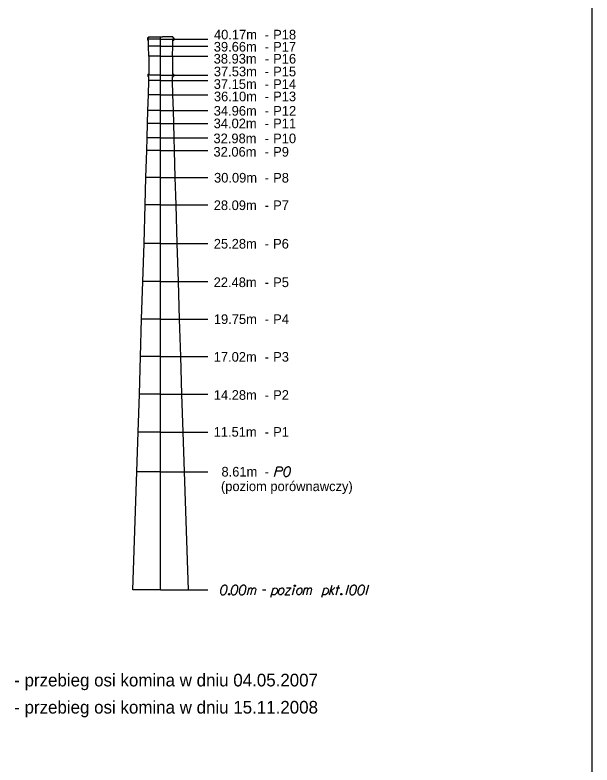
# Model space of a CAD drawing. Extents: x 138 to 264, y -75 to 121.
# Drawn here: x 180.87 to 190.1, y -57.33 to -45.34 of the extents above; entities that cross this region are included whole.
import ezdxf

# ---------------------------------------------------------------- set-up
doc = ezdxf.new("R2010")
doc.units = 0
doc.layers.add('Opisy', color=7, linetype='Continuous')
doc.layers.add('Ramka do drukowania', color=7, linetype='Continuous')

msp = doc.modelspace()

# ---------------------------------------------------------------- linework, layer by layer
at = {"layer": 'Opisy'}
for p, q in [((182.991, -45.703), (182.991, -45.721)), ((183.008, -45.703), (182.991, -45.703)), ((183.008, -45.684), (183.008, -45.703)), ((183.008, -45.684), (183.234, -45.684)), ((183.204, -54.531), (183.204, -45.684)), ((183.4, -45.684), (183.234, -45.684)), ((183.4, -45.684), (183.4, -45.703)), ((183.4, -45.703), (183.417, -45.703)), ((183.417, -45.703), (183.417, -45.721)), ((183.204, -45.721), (182.991, -45.721)), ((182.991, -45.721), (182.991, -45.74)), ((183.008, -45.74), (182.991, -45.74)), ((183.008, -45.834), (183.008, -45.74)), ((183.204, -45.721), (183.957, -45.721)), ((183.4, -45.74), (183.417, -45.74)), ((183.4, -45.834), (183.4, -45.74)), ((183.417, -45.721), (183.417, -45.74)), ((183.204, -45.834), (183.008, -45.834)), ((183.014, -45.994), (183.008, -45.834)), ((183.204, -45.834), (183.957, -45.834)), ((183.394, -45.994), (183.4, -45.834)), ((183.204, -45.994), (183.014, -45.994)), ((183.014, -45.994), (183.014, -46.282)), ((183.204, -45.994), (183.957, -45.994)), ((183.394, -45.994), (183.394, -46.282)), ((183.001, -46.282), (183.001, -46.301)), ((183.001, -46.282), (183.014, -46.282)), ((183.204, -46.301), (183.001, -46.301)), ((183.001, -46.301), (183.001, -46.321)), ((183.204, -46.301), (183.957, -46.301)), ((183.407, -46.282), (183.394, -46.282)), ((183.407, -46.282), (183.407, -46.301)), ((183.407, -46.301), (183.407, -46.321)), ((183.016, -46.321), (183.001, -46.321)), ((183.008, -46.615), (183.014, -46.384)), ((183.014, -46.384), (183.016, -46.321)), ((183.204, -46.384), (183.014, -46.384)), ((183.204, -46.384), (183.957, -46.384)), ((183.394, -46.384), (183.392, -46.321)), ((183.392, -46.321), (183.407, -46.321)), ((183.4, -46.615), (183.394, -46.384)), ((183.001, -46.866), (183.008, -46.615)), ((183.204, -46.615), (183.008, -46.615)), ((183.204, -46.615), (183.957, -46.615)), ((183.407, -46.866), (183.4, -46.615)), ((182.994, -47.071), (183.001, -46.866)), ((183.204, -46.866), (183.001, -46.866)), ((183.204, -46.866), (183.957, -46.866)), ((183.413, -47.071), (183.407, -46.866)), ((182.989, -47.299), (182.994, -47.071)), ((183.204, -47.071), (182.994, -47.071)), ((183.204, -47.071), (183.957, -47.071)), ((183.419, -47.299), (183.413, -47.071)), ((182.981, -47.501), (182.989, -47.299)), ((183.204, -47.299), (182.989, -47.299)), ((183.204, -47.299), (183.957, -47.299)), ((183.426, -47.501), (183.419, -47.299)), ((182.969, -47.933), (182.981, -47.501)), ((183.204, -47.501), (182.981, -47.501)), ((183.204, -47.501), (183.957, -47.501)), ((183.438, -47.933), (183.426, -47.501)), ((182.956, -48.371), (182.969, -47.933)), ((183.204, -47.933), (182.969, -47.933)), ((183.204, -47.933), (183.957, -47.933)), ((183.452, -48.371), (183.438, -47.933)), ((182.939, -48.989), (182.956, -48.371)), ((183.204, -48.371), (182.956, -48.371)), ((183.204, -48.371), (183.957, -48.371)), ((183.469, -48.989), (183.452, -48.371)), ((182.919, -49.601), (182.939, -48.989)), ((183.204, -48.989), (182.939, -48.989)), ((183.204, -48.989), (183.957, -48.989)), ((183.489, -49.601), (183.469, -48.989)), ((182.9, -50.2), (182.919, -49.601)), ((183.204, -49.601), (182.919, -49.601)), ((183.204, -49.601), (183.957, -49.601)), ((183.508, -50.2), (183.489, -49.601)), ((182.882, -50.798), (182.9, -50.2)), ((183.204, -50.2), (182.9, -50.2)), ((183.204, -50.2), (183.957, -50.2)), ((183.526, -50.798), (183.508, -50.2)), ((182.863, -51.4), (182.882, -50.798)), ((183.204, -50.798), (182.882, -50.798)), ((183.204, -50.798), (183.957, -50.798)), ((183.545, -51.4), (183.526, -50.798)), ((182.843, -52.006), (182.863, -51.4)), ((183.204, -51.4), (182.863, -51.4)), ((183.204, -51.4), (183.957, -51.4)), ((183.565, -52.006), (183.545, -51.4)), ((182.761, -54.531), (182.843, -52.006)), ((183.204, -52.006), (182.843, -52.006)), ((183.204, -52.006), (183.957, -52.006)), ((183.647, -54.531), (183.565, -52.006)), ((183.204, -52.643), (182.822, -52.643)), ((183.204, -52.643), (183.957, -52.643)), ((183.204, -54.531), (182.761, -54.531)), ((183.204, -54.531), (183.957, -54.531))]:
    msp.add_line(p, q, dxfattribs=at)
for points in [[(185.026, -52.718), (185.067, -52.563), (185.12, -52.563), (185.127, -52.565), (185.13, -52.566), (185.138, -52.57), (185.143, -52.573), (185.146, -52.578), (185.15, -52.584), (185.152, -52.593), (185.154, -52.6), (185.152, -52.606), (185.151, -52.611), (185.149, -52.616), (185.146, -52.619), (185.143, -52.624), (185.138, -52.628), (185.134, -52.63), (185.128, -52.633), (185.122, -52.634), (185.049, -52.634)], [(185.247, -52.563), (185.245, -52.563), (185.237, -52.565), (185.232, -52.566), (185.229, -52.567), (185.223, -52.57), (185.215, -52.573), (185.209, -52.577), (185.203, -52.582), (185.2, -52.587), (185.196, -52.593), (185.192, -52.599), (185.189, -52.606), (185.186, -52.611), (185.184, -52.618), (185.18, -52.63), (185.177, -52.648), (185.174, -52.663), (185.174, -52.676), (185.175, -52.686), (185.18, -52.697), (185.184, -52.703), (185.19, -52.71), (185.197, -52.715), (185.201, -52.716), (185.208, -52.718), (185.214, -52.718), (185.224, -52.716), (185.232, -52.714), (185.239, -52.71), (185.247, -52.704), (185.251, -52.701), (185.256, -52.696), (185.259, -52.691), (185.262, -52.687), (185.264, -52.681), (185.265, -52.679), (185.268, -52.673), (185.27, -52.665), (185.272, -52.658), (185.274, -52.653), (185.275, -52.65), (185.276, -52.645), (185.279, -52.634), (185.28, -52.628), (185.281, -52.622), (185.282, -52.613), (185.283, -52.602), (185.283, -52.599), (185.282, -52.594), (185.281, -52.589), (185.277, -52.582), (185.274, -52.577), (185.27, -52.573), (185.265, -52.57), (185.26, -52.567), (185.257, -52.566), (185.253, -52.565), (185.247, -52.563)], [(184.233, -54.456), (184.231, -54.456), (184.223, -54.457), (184.219, -54.458), (184.215, -54.46), (184.209, -54.462), (184.202, -54.466), (184.196, -54.469), (184.189, -54.474), (184.186, -54.479), (184.182, -54.485), (184.179, -54.491), (184.175, -54.498), (184.172, -54.503), (184.17, -54.51), (184.166, -54.523), (184.163, -54.541), (184.16, -54.555), (184.16, -54.569), (184.162, -54.578), (184.166, -54.589), (184.17, -54.595), (184.176, -54.603), (184.183, -54.608), (184.187, -54.609), (184.194, -54.61), (184.2, -54.61), (184.21, -54.609), (184.219, -54.606), (184.225, -54.603), (184.233, -54.597), (184.237, -54.593), (184.242, -54.588), (184.245, -54.583), (184.248, -54.58), (184.25, -54.574), (184.251, -54.571), (184.254, -54.565), (184.256, -54.558), (184.259, -54.551), (184.26, -54.546), (184.261, -54.542), (184.262, -54.537), (184.265, -54.526), (184.266, -54.52), (184.267, -54.514), (184.268, -54.506), (184.27, -54.495), (184.27, -54.491), (184.268, -54.486), (184.267, -54.481), (184.263, -54.474), (184.26, -54.469), (184.256, -54.466), (184.251, -54.462), (184.246, -54.46), (184.243, -54.458), (184.239, -54.457), (184.233, -54.456)], [(184.404, -54.456), (184.402, -54.456), (184.395, -54.457), (184.39, -54.458), (184.386, -54.46), (184.38, -54.462), (184.373, -54.466), (184.367, -54.469), (184.361, -54.474), (184.357, -54.479), (184.353, -54.485), (184.35, -54.491), (184.346, -54.498), (184.344, -54.503), (184.341, -54.51), (184.338, -54.523), (184.334, -54.541), (184.331, -54.555), (184.331, -54.569), (184.333, -54.578), (184.338, -54.589), (184.341, -54.595), (184.347, -54.603), (184.355, -54.608), (184.358, -54.609), (184.365, -54.61), (184.372, -54.61), (184.381, -54.609), (184.39, -54.606), (184.396, -54.603), (184.404, -54.597), (184.408, -54.593), (184.413, -54.588), (184.416, -54.583), (184.419, -54.58), (184.421, -54.574), (184.422, -54.571), (184.425, -54.565), (184.427, -54.558), (184.43, -54.551), (184.431, -54.546), (184.432, -54.542), (184.433, -54.537), (184.436, -54.526), (184.437, -54.52), (184.438, -54.514), (184.439, -54.506), (184.441, -54.495), (184.441, -54.491), (184.439, -54.486), (184.438, -54.481), (184.435, -54.474), (184.431, -54.469), (184.427, -54.466), (184.422, -54.462), (184.418, -54.46), (184.414, -54.458), (184.41, -54.457), (184.404, -54.456)], [(184.534, -54.456), (184.532, -54.456), (184.524, -54.457), (184.52, -54.458), (184.516, -54.46), (184.51, -54.462), (184.503, -54.466), (184.497, -54.469), (184.49, -54.474), (184.487, -54.479), (184.483, -54.485), (184.48, -54.491), (184.476, -54.498), (184.473, -54.503), (184.471, -54.51), (184.467, -54.523), (184.464, -54.541), (184.461, -54.555), (184.461, -54.569), (184.463, -54.578), (184.467, -54.589), (184.471, -54.595), (184.477, -54.603), (184.484, -54.608), (184.488, -54.609), (184.495, -54.61), (184.501, -54.61), (184.511, -54.609), (184.52, -54.606), (184.526, -54.603), (184.534, -54.597), (184.538, -54.593), (184.543, -54.588), (184.546, -54.583), (184.549, -54.58), (184.551, -54.574), (184.552, -54.571), (184.555, -54.565), (184.557, -54.558), (184.56, -54.551), (184.561, -54.546), (184.562, -54.542), (184.563, -54.537), (184.566, -54.526), (184.567, -54.52), (184.568, -54.514), (184.569, -54.506), (184.571, -54.495), (184.571, -54.491), (184.569, -54.486), (184.568, -54.481), (184.565, -54.474), (184.561, -54.469), (184.557, -54.466), (184.552, -54.462), (184.548, -54.46), (184.544, -54.458), (184.54, -54.457), (184.534, -54.456)], [(185.349, -54.456), (185.355, -54.456), (185.358, -54.458), (185.362, -54.463), (185.362, -54.469), (185.358, -54.474), (185.355, -54.477), (185.349, -54.477), (185.345, -54.474), (185.341, -54.469), (185.341, -54.463), (185.345, -54.458), (185.349, -54.456)], [(185.905, -54.61), (185.946, -54.456)], [(186.013, -54.61), (186.053, -54.456)], [(186.208, -54.456), (186.167, -54.61)], [(186.302, -54.456), (186.299, -54.456), (186.292, -54.457), (186.287, -54.458), (186.283, -54.46), (186.277, -54.462), (186.27, -54.466), (186.264, -54.469), (186.258, -54.474), (186.254, -54.479), (186.251, -54.485), (186.247, -54.491), (186.243, -54.498), (186.241, -54.503), (186.238, -54.51), (186.235, -54.523), (186.231, -54.541), (186.229, -54.555), (186.229, -54.569), (186.23, -54.578), (186.235, -54.589), (186.238, -54.595), (186.245, -54.603), (186.252, -54.608), (186.255, -54.609), (186.263, -54.61), (186.269, -54.61), (186.279, -54.609), (186.287, -54.606), (186.293, -54.603), (186.302, -54.597), (186.305, -54.593), (186.31, -54.588), (186.314, -54.583), (186.316, -54.58), (186.319, -54.574), (186.32, -54.571), (186.322, -54.565), (186.325, -54.558), (186.327, -54.551), (186.328, -54.546), (186.33, -54.542), (186.331, -54.537), (186.333, -54.526), (186.334, -54.52), (186.336, -54.514), (186.337, -54.506), (186.338, -54.495), (186.338, -54.491), (186.337, -54.486), (186.336, -54.481), (186.332, -54.474), (186.328, -54.469), (186.325, -54.466), (186.32, -54.462), (186.315, -54.46), (186.311, -54.458), (186.308, -54.457), (186.302, -54.456)], [(186.431, -54.456), (186.429, -54.456), (186.422, -54.457), (186.417, -54.458), (186.413, -54.46), (186.407, -54.462), (186.4, -54.466), (186.394, -54.469), (186.388, -54.474), (186.384, -54.479), (186.38, -54.485), (186.377, -54.491), (186.373, -54.498), (186.371, -54.503), (186.368, -54.51), (186.365, -54.523), (186.361, -54.541), (186.359, -54.555), (186.359, -54.569), (186.36, -54.578), (186.365, -54.589), (186.368, -54.595), (186.374, -54.603), (186.382, -54.608), (186.385, -54.609), (186.393, -54.61), (186.399, -54.61), (186.408, -54.609), (186.417, -54.606), (186.423, -54.603), (186.431, -54.597), (186.435, -54.593), (186.44, -54.588), (186.444, -54.583), (186.446, -54.58), (186.448, -54.574), (186.45, -54.571), (186.452, -54.565), (186.455, -54.558), (186.457, -54.551), (186.458, -54.546), (186.459, -54.542), (186.461, -54.537), (186.463, -54.526), (186.464, -54.52), (186.465, -54.514), (186.467, -54.506), (186.468, -54.495), (186.468, -54.491), (186.467, -54.486), (186.465, -54.481), (186.462, -54.474), (186.458, -54.469), (186.455, -54.466), (186.45, -54.462), (186.445, -54.46), (186.441, -54.458), (186.438, -54.457), (186.431, -54.456)], [(186.53, -54.456), (186.489, -54.61)], [(184.591, -54.61), (184.619, -54.5)], [(184.612, -54.529), (184.618, -54.515), (184.624, -54.508), (184.631, -54.503), (184.639, -54.5), (184.643, -54.497), (184.651, -54.497), (184.653, -54.498), (184.658, -54.503), (184.663, -54.509), (184.666, -54.52), (184.668, -54.526), (184.674, -54.515), (184.681, -54.508), (184.688, -54.503), (184.696, -54.5), (184.702, -54.497), (184.708, -54.497), (184.713, -54.498), (184.716, -54.503), (184.72, -54.509), (184.724, -54.52), (184.725, -54.526), (184.704, -54.61)], [(184.647, -54.61), (184.668, -54.526)], [(184.834, -54.532), (184.886, -54.532)], [(184.969, -54.65), (185.01, -54.498)], [(185.006, -54.512), (185.019, -54.502), (185.037, -54.498), (185.051, -54.501), (185.061, -54.508), (185.068, -54.518), (185.073, -54.531), (185.074, -54.543), (185.072, -54.554), (185.068, -54.568), (185.059, -54.582), (185.047, -54.595), (185.028, -54.608), (185.013, -54.61), (184.998, -54.609), (184.982, -54.6)], [(185.142, -54.498), (185.151, -54.498), (185.161, -54.503), (185.17, -54.517), (185.172, -54.523), (185.173, -54.529), (185.173, -54.534), (185.173, -54.552), (185.169, -54.564), (185.163, -54.578), (185.156, -54.591), (185.144, -54.602), (185.133, -54.61), (185.115, -54.61), (185.107, -54.608), (185.1, -54.602), (185.096, -54.595), (185.091, -54.581), (185.091, -54.559), (185.094, -54.552), (185.099, -54.536), (185.104, -54.527), (185.106, -54.523), (185.118, -54.509), (185.13, -54.502), (185.142, -54.498)], [(185.215, -54.496), (185.294, -54.496), (185.193, -54.61), (185.271, -54.61)], [(185.315, -54.61), (185.346, -54.492)], [(185.434, -54.498), (185.442, -54.498), (185.452, -54.503), (185.462, -54.517), (185.463, -54.523), (185.464, -54.529), (185.464, -54.534), (185.464, -54.552), (185.46, -54.564), (185.454, -54.578), (185.447, -54.591), (185.435, -54.602), (185.424, -54.61), (185.406, -54.61), (185.399, -54.608), (185.391, -54.602), (185.388, -54.595), (185.383, -54.581), (185.383, -54.559), (185.385, -54.552), (185.39, -54.536), (185.395, -54.527), (185.397, -54.523), (185.409, -54.509), (185.422, -54.502), (185.434, -54.498)], [(185.485, -54.61), (185.513, -54.5)], [(185.505, -54.529), (185.511, -54.515), (185.517, -54.508), (185.525, -54.503), (185.532, -54.5), (185.537, -54.497), (185.544, -54.497), (185.547, -54.498), (185.551, -54.503), (185.556, -54.509), (185.56, -54.52), (185.561, -54.526), (185.567, -54.515), (185.575, -54.508), (185.582, -54.503), (185.589, -54.5), (185.595, -54.497), (185.601, -54.497), (185.606, -54.498), (185.61, -54.503), (185.613, -54.509), (185.617, -54.52), (185.618, -54.526), (185.598, -54.61)], [(185.541, -54.61), (185.561, -54.526)], [(185.782, -54.65), (185.823, -54.498)], [(185.82, -54.512), (185.832, -54.502), (185.85, -54.498), (185.865, -54.501), (185.874, -54.508), (185.882, -54.518), (185.887, -54.531), (185.888, -54.543), (185.885, -54.554), (185.882, -54.568), (185.872, -54.582), (185.86, -54.595), (185.842, -54.608), (185.826, -54.61), (185.811, -54.609), (185.795, -54.6)], [(185.919, -54.555), (185.992, -54.495)], [(185.934, -54.543), (185.965, -54.61)], [(186.013, -54.498), (186.071, -54.498)], [(184.297, -54.589), (184.304, -54.589), (184.307, -54.592), (184.311, -54.597), (184.311, -54.603), (184.307, -54.608), (184.304, -54.61), (184.297, -54.61), (184.294, -54.608), (184.29, -54.603), (184.29, -54.597), (184.294, -54.592), (184.297, -54.589)], [(186.092, -54.589), (186.098, -54.589), (186.101, -54.592), (186.105, -54.597), (186.105, -54.603), (186.101, -54.608), (186.098, -54.61), (186.092, -54.61), (186.088, -54.608), (186.084, -54.603), (186.084, -54.597), (186.088, -54.592), (186.092, -54.589)]]:
    msp.add_lwpolyline(points, dxfattribs=at)
at = {"layer": 'Ramka do drukowania'}
msp.add_line((190.105, -63.621), (190.105, -33.921), dxfattribs=at)

# ---------------------------------------------------------------- texts
at = {"layer": 'Opisy'}
for s, height, p in [('40.17m', 0.1542, (184.057, -45.727)), ('P18', 0.1542, (185.004, -45.727)), ('-', 0.154, (184.867, -45.727)), ('39.66m', 0.1542, (184.054, -45.921)), ('P17', 0.1542, (185.004, -45.921)), ('-', 0.154, (184.868, -45.921)), ('38.93m', 0.1542, (184.052, -46.113)), ('-', 0.154, (184.871, -46.113)), ('P16', 0.1542, (185.004, -46.113)), ('37.53m', 0.1542, (184.055, -46.317)), ('P15', 0.1542, (185.004, -46.317)), ('-', 0.154, (184.867, -46.317)), ('37.15m', 0.1542, (184.053, -46.518)), ('P14', 0.1542, (185.004, -46.518)), ('-', 0.154, (184.867, -46.518)), ('36.10m', 0.1542, (184.056, -46.716)), ('-', 0.154, (184.868, -46.716)), ('P13', 0.1542, (185.004, -46.716)), ('34.96m', 0.1542, (184.053, -46.946)), ('-', 0.154, (184.868, -46.946)), ('P12', 0.1542, (185.005, -46.946)), ('34.02m', 0.1542, (184.052, -47.147)), ('P11', 0.1542, (185.004, -47.147)), ('-', 0.154, (184.868, -47.147)), ('32.98m', 0.1542, (184.049, -47.387)), ('P10', 0.1542, (185.004, -47.387)), ('-', 0.154, (184.868, -47.387)), ('32.06m', 0.1542, (184.049, -47.601)), ('P9', 0.1542, (185.004, -47.601)), ('-', 0.154, (184.868, -47.601)), ('30.09m', 0.1542, (184.058, -48.016)), ('P8', 0.1542, (185.004, -48.017)), ('-', 0.154, (184.868, -48.016)), ('28.09m', 0.1542, (184.053, -48.456)), ('P7', 0.1542, (185.004, -48.456)), ('-', 0.154, (184.868, -48.456)), ('25.28m', 0.1542, (184.054, -49.072)), ('P6', 0.1542, (185.003, -49.072)), ('-', 0.154, (184.867, -49.072)), ('22.48m', 0.1542, (184.052, -49.688)), ('P5', 0.1542, (185.004, -49.688)), ('-', 0.154, (184.867, -49.688)), ('19.75m', 0.1542, (184.055, -50.278)), ('P4', 0.1542, (185.004, -50.278)), ('-', 0.154, (184.867, -50.278)), ('17.02m', 0.1542, (184.053, -50.881)), ('P3', 0.1542, (185.004, -50.881)), ('-', 0.154, (184.867, -50.881)), ('14.28m', 0.1542, (184.054, -51.491)), ('P2', 0.1542, (185.004, -51.491)), ('-', 0.154, (184.868, -51.491)), ('11.51m', 0.1542, (184.052, -52.081)), ('P1', 0.1542, (185.004, -52.081)), ('-', 0.154, (184.867, -52.081)), ('8.61m', 0.1542, (184.177, -52.718)), ('-', 0.154, (184.867, -52.718)), ('(poziom porównawczy)', 0.15416, (184.169, -52.951)), ('- przebieg osi komina w dniu 04.05.2007', 0.2024, (180.861, -56.075)), ('- przebieg osi komina w dniu 15.11.2008', 0.2024, (180.861, -56.509))]:
    msp.add_text(s, height=height, dxfattribs=at).set_placement(p)

doc.saveas('drawing.dxf')
